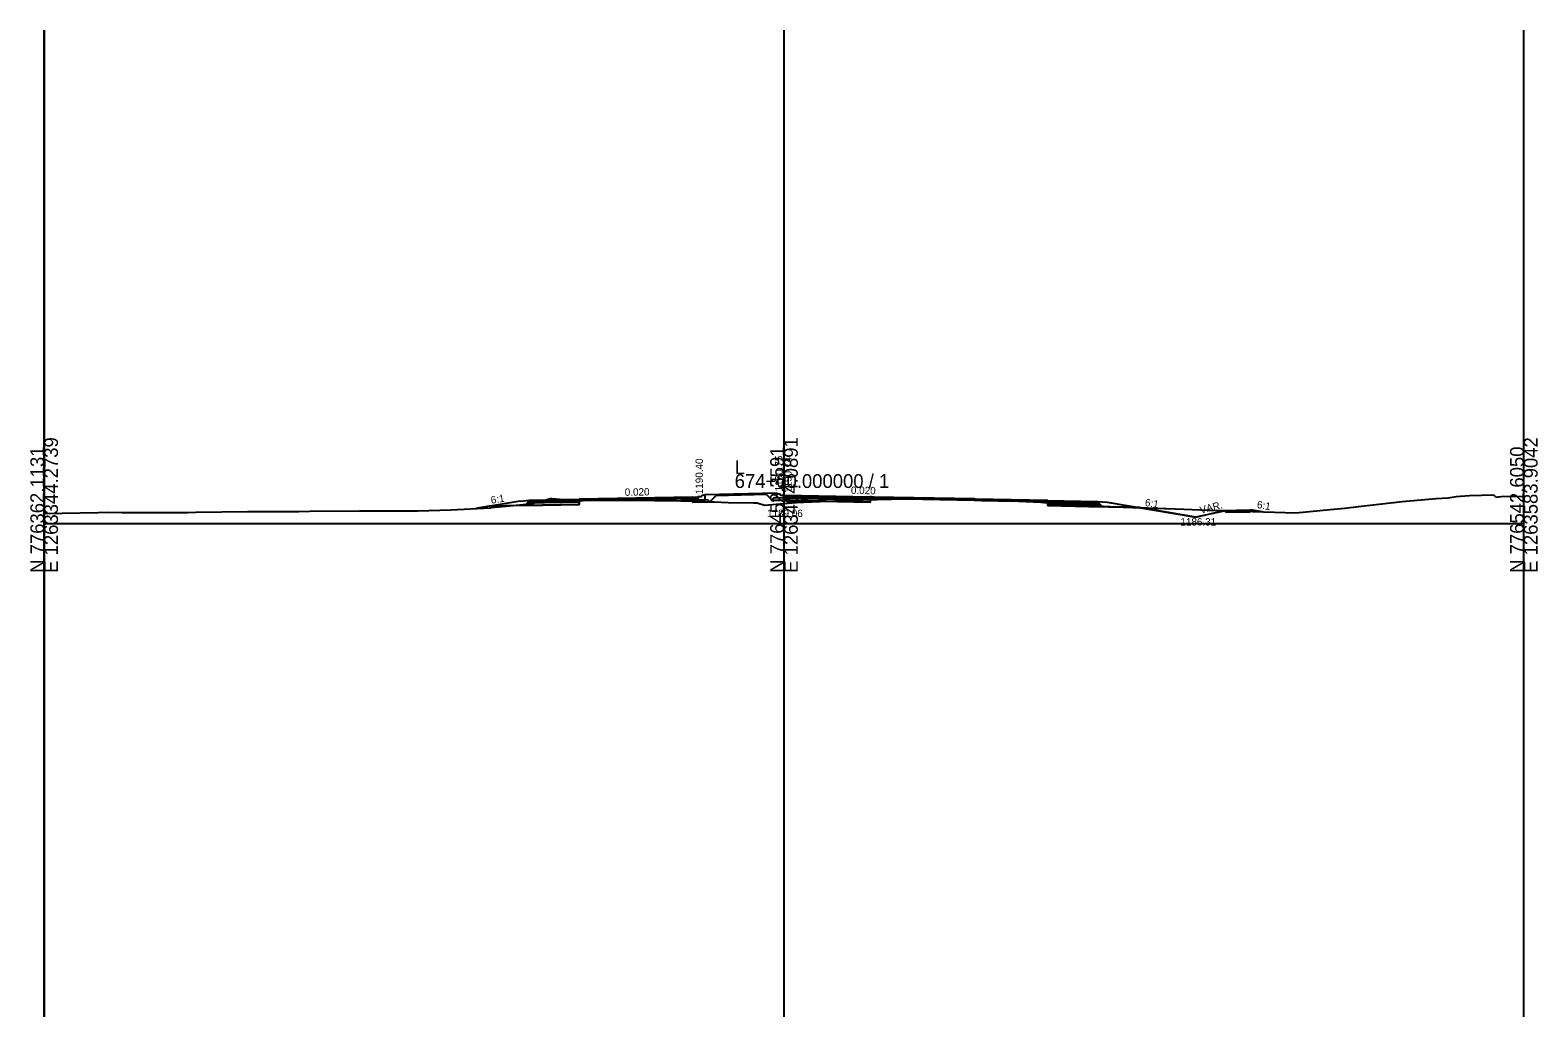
# Model space of a CAD drawing. Extents: x -41 to 1262860, y -100 to 777489.
# Drawn here: x 497.2 to 802.8, y 550 to 750 of the extents above; entities that cross this region are included whole.
import ezdxf

# ---------------------------------------------------------------- set-up
doc = ezdxf.new("R2010")
doc.units = 0
for name, color, linetype in [('Exist Cross Section Cell', 7, 'Continuous'), ('Exist XS Center Line Elevation Label', 7, 'Continuous'), ('Exist XS Ground Line', 7, 'Continuous'), ('Prop CMT Pvmt Concrete', 7, 'Continuous'), ('Prop CMT Pvmt Course 1', 7, 'Continuous'), ('Prop CMT Pvmt Course 4', 7, 'Continuous'), ('Prop CMT Pvmt Surface', 7, 'Continuous'), ('Prop CMT Shld Paved Course 1', 7, 'Continuous'), ('Prop CMT Shld Paved Course 2', 7, 'Continuous'), ('Prop CMT Shld Paved Course 4', 7, 'Continuous'), ('Prop CMT Subgrade Earthwork', 7, 'Continuous'), ('Prop Conc Curb and Gutter', 7, 'Continuous'), ('Prop Conc Island Cover', 7, 'Continuous'), ('Prop XS Ditch Standard Text', 7, 'Continuous'), ('Prop XS Earthwork Shape', 7, 'Continuous'), ('Prop XS Elevation Labels', 7, 'Continuous'), ('Prop XS Exc Vertical Line 1', 7, 'Continuous'), ('Prop XS Exc Vertical Line 2', 7, 'Continuous'), ('Prop XS Exc Vertical Line 3', 7, 'Continuous'), ('Prop XS Finish Grade', 7, 'Continuous'), ('Prop XS Hydro Elevations', 7, 'Continuous'), ('Prop XS SE Text', 7, 'Continuous'), ('Prop XS Side Slope Text', 7, 'Continuous'), ('Scratch_Level_1', 7, 'Continuous'), ('Scratch_Level_4', 7, 'Continuous'), ('Scratch_Level_6', 7, 'Continuous')]:
    doc.layers.add(name, color=color, linetype=linetype)

msp = doc.modelspace()

# ---------------------------------------------------------------- linework, layer by layer
at = {"layer": 'Exist Cross Section Cell'}
for p, q in [((650, 650), (650, 660)), ((500, 650), (650, 650)), ((650, 650), (800, 650))]:
    msp.add_line(p, q, dxfattribs=at)
at = {"layer": 'Exist XS Ground Line'}
msp.add_lwpolyline([(500, 652.04), (510.96, 652.26), (512.91, 652.27), (515.75, 652.23), (529.06, 652.25), (530.74, 652.28), (541.2, 652.41), (547.52, 652.46), (551.63, 652.45), (553.83, 652.47), (563.92, 652.6), (570.93, 652.58), (574.33, 652.55), (575.77, 652.57), (582.45, 652.79), (590.5, 653.2), (590.64, 653.21), (598.08, 653.95), (599.23, 654.15), (602.37, 654.95), (602.58, 655), (603, 654.97), (607.37, 654.58), (609.27, 654.68), (610.58, 654.78), (617.64, 654.7), (623.77, 654.69), (629.1, 654.57), (635.87, 654.4), (637.23, 654.34), (638.67, 654.28), (643.84, 654.18), (644.57, 654.17), (645.18, 653.99), (646.1, 653.71), (649.13, 653.99), (652.52, 654.26), (653.77, 654.34), (654, 654.35), (663.96, 654.73), (665.99, 654.81), (671.85, 654.94), (678.16, 655.09), (688.67, 654.92), (690.03, 654.9), (693.32, 654.74), (702.05, 654.32), (702.71, 654.28), (703.58, 654.22), (707.95, 653.88), (709.03, 653.79), (717.53, 653.39), (720.69, 653.27), (729.34, 652.94), (737.98, 652.62), (739.5, 652.6), (740.87, 652.53), (742.89, 652.49), (753.8, 652.18), (760.75, 652.87), (763.68, 653.09), (766.48, 653.44), (775.32, 654.47), (782.23, 655.1), (784.69, 655.21), (786.31, 655.44), (787.13, 655.57), (789, 655.65), (793.86, 655.81), (794.18, 655.49), (794.36, 655.31), (794.87, 655.42), (795.4, 655.44), (800, 655.53)], dxfattribs=at)
at = {"layer": 'Prop CMT Pvmt Concrete'}
for p, q in [((739.5, 652.6), (744.5, 652.7)), ((739.5, 652.6), (739.5, 652.27)), ((739.5, 652.27), (744.5, 652.37)), ((744.5, 652.7), (744.5, 652.37))]:
    msp.add_line(p, q, dxfattribs=at)
at = {"layer": 'Prop CMT Pvmt Course 1'}
for p, q in [((631.5, 655.12), (632.5, 655.14)), ((632.5, 655.14), (632.5, 655.39)), ((650.03, 655.74), (650.03, 655.49)), ((650.03, 655.49), (667.5, 655.14))]:
    msp.add_line(p, q, dxfattribs=at)
for points in [[(608.5, 654.91), (608.5, 654.66), (631.5, 655.12), (631.5, 655.12), (631.5, 655.37), (631.5, 655.37), (631.5, 655.37), (608.5, 654.91), (608.5, 654.91)], [(703.5, 654.67), (703.5, 654.67), (688.66, 654.96), (688.66, 654.96), (688.56, 654.97), (688.56, 654.97), (668.18, 655.37), (668.18, 655.37), (667.79, 655.38), (667.79, 655.38), (667.5, 655.39), (667.5, 655.39), (667.5, 655.14), (667.79, 655.13), (667.79, 655.13), (668.18, 655.12), (668.18, 655.12), (688.56, 654.72), (688.56, 654.72), (688.66, 654.71), (688.66, 654.71), (703.5, 654.42), (703.5, 654.67)]]:
    msp.add_lwpolyline(points, dxfattribs=at)
at = {"layer": 'Prop CMT Pvmt Course 4'}
for p, q in [((608.5, 653.87), (593.44, 653.56)), ((597.9, 654.11), (597.44, 653.64))]:
    msp.add_line(p, q, dxfattribs=at)
at = {"layer": 'Prop CMT Pvmt Surface'}
for p, q in [((598.5, 654.71), (608.5, 654.91)), ((608.5, 654.91), (631.5, 655.37)), ((631.5, 655.37), (632.5, 655.39)), ((650.03, 655.74), (667.5, 655.39)), ((667.5, 655.39), (703.5, 654.67)), ((703.5, 654.67), (713.5, 654.47))]:
    msp.add_line(p, q, dxfattribs=at)
at = {"layer": 'Prop CMT Shld Paved Course 1'}
for p, q in [((598.5, 654.71), (598.24, 654.45)), ((608.5, 654.66), (598.24, 654.45)), ((604.5, 654.83), (604.5, 654.83)), ((608.5, 654.91), (608.5, 654.66)), ((608.5, 654.66), (608.5, 654.66)), ((703.5, 654.67), (703.5, 654.42)), ((703.5, 654.42), (703.5, 654.42)), ((703.5, 654.42), (713.76, 654.21)), ((707.5, 654.59), (707.5, 654.59)), ((713.76, 654.21), (713.5, 654.47))]:
    msp.add_line(p, q, dxfattribs=at)
at = {"layer": 'Prop CMT Shld Paved Course 2'}
for p, q in [((597.9, 654.11), (598.24, 654.45)), ((608.5, 654.32), (597.9, 654.11)), ((603.9, 654.23), (603.9, 654.23)), ((603.9, 654.23), (603.9, 654.23)), ((609.27, 654.67), (608.5, 654.66)), ((608.5, 654.64), (608.92, 654.67)), ((608.5, 654.66), (608.5, 654.32)), ((608.5, 654.66), (608.5, 654.66)), ((608.5, 654.66), (608.5, 654.64)), ((608.5, 654.32), (608.5, 654.32)), ((608.92, 654.67), (608.92, 654.67)), ((608.92, 654.67), (609.27, 654.67)), ((610.58, 654.7), (609.27, 654.67)), ((609.27, 654.67), (610.58, 654.7)), ((609.27, 654.67), (609.27, 654.67)), ((609.27, 654.67), (609.27, 654.67)), ((617.64, 654.84), (610.58, 654.7)), ((610.58, 654.7), (613.13, 654.75)), ((610.58, 654.7), (610.58, 654.7)), ((610.58, 654.7), (610.58, 654.7)), ((613.13, 654.75), (613.13, 654.75)), ((613.13, 654.75), (617.64, 654.7)), ((623.77, 654.96), (617.64, 654.84)), ((617.64, 654.84), (617.64, 654.84)), ((617.64, 654.7), (617.64, 654.7)), ((617.64, 654.7), (623.77, 654.69)), ((629.1, 655.07), (623.77, 654.96)), ((623.77, 654.69), (625.16, 654.66)), ((625.16, 654.66), (629.1, 654.74)), ((625.16, 654.66), (625.16, 654.66)), ((631.5, 655.12), (629.1, 655.07)), ((629.1, 655.07), (629.1, 655.07)), ((629.1, 654.74), (631.5, 654.78)), ((629.1, 654.74), (629.1, 654.74)), ((631.5, 654.78), (631.5, 655.12)), ((631.5, 655.12), (631.5, 655.12)), ((631.5, 654.78), (632.5, 654.8)), ((632.5, 655.14), (632.5, 654.8)), ((650.03, 655.15), (650.03, 655.49)), ((650.03, 655.15), (667.5, 654.8)), ((667.79, 655.13), (667.5, 655.14)), ((667.5, 655.14), (667.5, 655.14)), ((667.5, 655.14), (667.5, 655.14)), ((667.5, 655.14), (667.5, 654.84)), ((667.5, 654.84), (667.79, 654.85)), ((667.5, 654.84), (667.5, 654.8)), ((667.5, 654.84), (667.5, 654.84)), ((668.18, 655.12), (667.79, 655.13)), ((667.79, 654.85), (668.18, 654.86)), ((671.85, 655.05), (668.18, 655.12)), ((668.18, 655.12), (668.18, 655.12)), ((668.18, 654.86), (671.85, 654.94)), ((668.18, 654.86), (668.18, 654.86)), ((678.16, 654.92), (671.85, 655.05)), ((671.85, 655.05), (671.85, 655.05)), ((671.85, 655.05), (671.85, 655.05)), ((671.85, 654.94), (674.37, 655)), ((671.85, 654.94), (671.85, 654.94)), ((671.85, 654.94), (671.85, 654.94)), ((674.37, 655), (674.37, 655)), ((674.37, 655), (678.16, 654.92)), ((688.56, 654.72), (678.16, 654.92)), ((678.16, 654.92), (678.16, 654.92)), ((678.16, 654.92), (678.16, 654.92)), ((678.16, 654.92), (678.16, 654.92)), ((678.16, 654.92), (678.16, 654.92)), ((678.16, 654.92), (688.56, 654.72)), ((688.66, 654.71), (688.56, 654.72)), ((688.56, 654.72), (688.56, 654.72)), ((688.56, 654.72), (688.56, 654.72)), ((688.56, 654.72), (688.66, 654.71)), ((688.67, 654.71), (688.66, 654.71)), ((688.66, 654.71), (688.67, 654.71)), ((690.03, 654.69), (688.67, 654.71)), ((688.67, 654.71), (688.67, 654.71)), ((688.67, 654.71), (688.67, 654.71)), ((688.67, 654.71), (690.03, 654.69)), ((693.32, 654.62), (690.03, 654.69)), ((690.03, 654.69), (693.32, 654.62)), ((702.05, 654.45), (693.32, 654.62)), ((693.32, 654.62), (693.32, 654.62)), ((693.32, 654.62), (693.32, 654.62)), ((693.32, 654.62), (697.56, 654.54)), ((697.56, 654.54), (697.56, 654.54)), ((697.56, 654.54), (702.05, 654.32)), ((702.71, 654.43), (702.05, 654.45)), ((702.05, 654.45), (702.05, 654.45)), ((702.05, 654.45), (702.05, 654.45)), ((702.05, 654.32), (702.05, 654.32)), ((702.05, 654.32), (702.05, 654.32)), ((702.05, 654.32), (702.71, 654.28)), ((703.5, 654.42), (702.71, 654.43)), ((702.71, 654.43), (702.71, 654.43)), ((702.71, 654.28), (702.71, 654.28)), ((702.71, 654.28), (703.5, 654.23)), ((703.5, 654.42), (703.5, 654.08)), ((703.5, 654.23), (703.5, 654.42)), ((703.5, 654.42), (703.5, 654.42)), ((703.5, 654.42), (703.5, 654.42)), ((703.5, 654.23), (703.5, 654.23)), ((714.1, 653.87), (713.76, 654.21)), ((703.5, 654.08), (703.5, 654.08)), ((703.5, 654.08), (714.1, 653.87))]:
    msp.add_line(p, q, dxfattribs=at)
at = {"layer": 'Prop CMT Shld Paved Course 4'}
for p, q in [((603.9, 654.23), (603.9, 654.23)), ((608.5, 654.32), (608.5, 653.87)), ((625.16, 654.66), (629.1, 654.57)), ((629.1, 654.57), (631.5, 654.51)), ((631.5, 654.78), (631.5, 654.32)), ((631.5, 654.32), (634.95, 654.39)), ((632.5, 654.8), (634.5, 654.84)), ((634.5, 654.84), (634.95, 654.39)), ((648.03, 655.19), (647.58, 654.74)), ((647.58, 654.74), (667.5, 654.34)), ((650.03, 655.15), (648.03, 655.19)), ((667.5, 654.8), (667.5, 654.34)), ((703.5, 654.08), (703.5, 653.63)), ((703.5, 653.63), (714.56, 653.4)), ((714.56, 653.4), (714.1, 653.87))]:
    msp.add_line(p, q, dxfattribs=at)
at = {"layer": 'Prop CMT Subgrade Earthwork'}
for p, q in [((608.5, 653.87), (608.5, 654.64)), ((631.5, 654.32), (631.5, 654.51)), ((634.95, 654.39), (631.5, 654.32)), ((634.95, 654.39), (636.45, 655.89)), ((647.58, 654.74), (646.2, 656.13)), ((647.58, 654.74), (667.5, 654.34)), ((667.5, 654.34), (667.5, 654.84)), ((703.5, 654.23), (703.5, 653.63)), ((608.5, 653.87), (590.22, 653.5)), ((703.5, 653.63), (721.78, 653.26))]:
    msp.add_line(p, q, dxfattribs=at)
at = {"layer": 'Prop Conc Curb and Gutter'}
for p, q in [((633.19, 655.4), (632.5, 655.39)), ((632.5, 655.39), (632.5, 654.8)), ((632.5, 654.8), (634, 654.83)), ((633.25, 655.48), (633.25, 655.46)), ((634, 655.83), (633.35, 655.62)), ((634, 654.83), (634, 655.83)), ((634, 654.83), (634, 654.83)), ((648.53, 656.18), (649.18, 655.97)), ((648.53, 655.18), (648.53, 656.18)), ((650.03, 655.15), (648.53, 655.18)), ((649.28, 655.83), (649.28, 655.81)), ((649.34, 655.75), (650.03, 655.74)), ((650.03, 655.15), (650.03, 655.74))]:
    msp.add_line(p, q, dxfattribs=at)
for centre, radius, start, end in [((633.19, 655.46), 0.0625, 271.1458, 360), ((633.4, 655.48), 0.146, 108.435, 180), ((649.13, 655.83), 0.146, 0, 71.565), ((649.34, 655.81), 0.0625, 180, 268.8542)]:
    msp.add_arc(centre, radius, start, end, dxfattribs=at)
at = {"layer": 'Prop Conc Island Cover'}
for p, q in [((648.53, 656.18), (634, 655.83)), ((634, 655.57), (634, 655.57))]:
    msp.add_line(p, q, dxfattribs=at)
at = {"layer": 'Prop XS Earthwork Shape'}
for points in [[(597.71, 653.92), (597.44, 653.64), (608.5, 653.87), (608.5, 654.64), (607.37, 654.58), (603, 654.97), (602.58, 655), (602.37, 654.95), (599.23, 654.15), (598.08, 653.95)], [(634.95, 654.39), (631.5, 654.32), (631.5, 654.51), (634.97, 654.42)], [(647.58, 654.74), (646.44, 655.88), (636.19, 655.64), (634.97, 654.42), (635.87, 654.4), (637.23, 654.34), (638.67, 654.28), (643.84, 654.18), (644.57, 654.17), (645.18, 653.99), (646.1, 653.71), (649.13, 653.99), (652.52, 654.26), (653.77, 654.34), (654, 654.35), (658.5, 654.52)], [(658.5, 654.52), (663.96, 654.73), (665.99, 654.81), (667.5, 654.84), (667.5, 654.34)], [(707.95, 653.88), (709.03, 653.79), (714.43, 653.53), (714.56, 653.4), (703.5, 653.63), (703.5, 654.23), (703.58, 654.22)], [(587.51, 653.05), (590.5, 653.2), (590.64, 653.21), (594.36, 653.58), (590.22, 653.5)], [(597.71, 653.92), (597.44, 653.64), (594.36, 653.58)], [(717.53, 653.39), (720.24, 653.29), (714.56, 653.4), (714.43, 653.53)], [(720.24, 653.29), (720.69, 653.27), (721.99, 653.22), (721.78, 653.26)], [(721.99, 653.22), (729.34, 652.94), (737.98, 652.62), (739.5, 652.6), (733.5, 651.31)], [(739.5, 652.6), (740.87, 652.53), (742.89, 652.49), (747.04, 652.37), (745, 652.71), (744.5, 652.7)]]:
    msp.add_lwpolyline(points, close=True, dxfattribs=at)
at = {"layer": 'Prop XS Exc Vertical Line 1'}
msp.add_line((500, 550), (500, 750), dxfattribs=at)
at = {"layer": 'Prop XS Exc Vertical Line 2'}
msp.add_line((650, 550), (650, 750), dxfattribs=at)
at = {"layer": 'Prop XS Exc Vertical Line 3'}
msp.add_line((800, 550), (800, 750), dxfattribs=at)
at = {"layer": 'Prop XS Finish Grade'}
for p, q in [((596.5, 654.55), (587.51, 653.05)), ((596.5, 654.55), (598.5, 654.71)), ((598.5, 654.71), (597.44, 653.64)), ((713.5, 654.47), (715.5, 654.31)), ((713.5, 654.47), (714.56, 653.4)), ((715.5, 654.31), (733.5, 651.31)), ((733.5, 651.31), (739, 652.59)), ((744.5, 652.7), (739, 652.59)), ((744.5, 652.7), (745, 652.71)), ((745, 652.71), (747.04, 652.37))]:
    msp.add_line(p, q, dxfattribs=at)
at = {"layer": 'Scratch_Level_1'}
msp.add_lwpolyline([(744.5, 652.7), (739.5, 652.6), (737.78, 652.63)], dxfattribs=at)
at = {"layer": 'Scratch_Level_4'}
msp.add_line((800, 550), (800, 750), dxfattribs=at)
at = {"layer": 'Scratch_Level_6'}
msp.add_line((500, 750), (500, 550), dxfattribs=at)

# ---------------------------------------------------------------- texts
at = {"layer": 'Exist Cross Section Cell'}
for s, p in [('E 1263344.2739', (502.8, 640)), ('E 1263464.0891', (652.8, 640)), ('E 1263583.9042', (802.8, 640)), ('N 776362.1131', (500, 640)), ('N 776452.3591', (650, 640)), ('N 776542.6050', (800, 640))]:
    msp.add_text(s, height=2.8, rotation=90, dxfattribs=at).set_placement(p)
for s, p in [('L', (640, 660)), ('674+00.000000 / 1', (640, 657.2))]:
    msp.add_text(s, height=2.8, dxfattribs=at).set_placement(p)
at = {"layer": 'Exist XS Center Line Elevation Label'}
msp.add_text('1189.06', height=1.5, dxfattribs=at).set_placement((646.56, 651.31))
at = {"layer": 'Prop XS Ditch Standard Text'}
msp.add_text('1186.31', height=1.5, dxfattribs=at).set_placement((730.37, 649.59))
at = {"layer": 'Prop XS Elevation Labels'}
for s, p in [('1190.75', (649.7, 656.5)), ('1190.40', (633.56, 655.93))]:
    msp.add_text(s, height=1.5, rotation=90, dxfattribs=at).set_placement(p)
at = {"layer": 'Prop XS Hydro Elevations'}
msp.add_text('1190.74', height=1.5, rotation=90, dxfattribs=at).set_placement((651.55, 656.2))
at = {"layer": 'Prop XS SE Text'}
for rotation, p in [(1.1458, (617.73, 655.6)), (358.8542, (663.55, 656.01))]:
    msp.add_text('0.020', height=1.5, rotation=rotation, dxfattribs=at).set_placement(p)
at = {"layer": 'Prop XS Side Slope Text'}
for s, rotation, p in [('6:1', 9.4623, (590.68, 653.98)), ('6:1', 350.5377, (723.09, 653.58)), ('VAR.', 14.2871, (734.51, 651.96)), ('6:1', 350.5377, (745.8, 653.15))]:
    msp.add_text(s, height=1.5, rotation=rotation, dxfattribs=at).set_placement(p)

doc.saveas('drawing.dxf')
